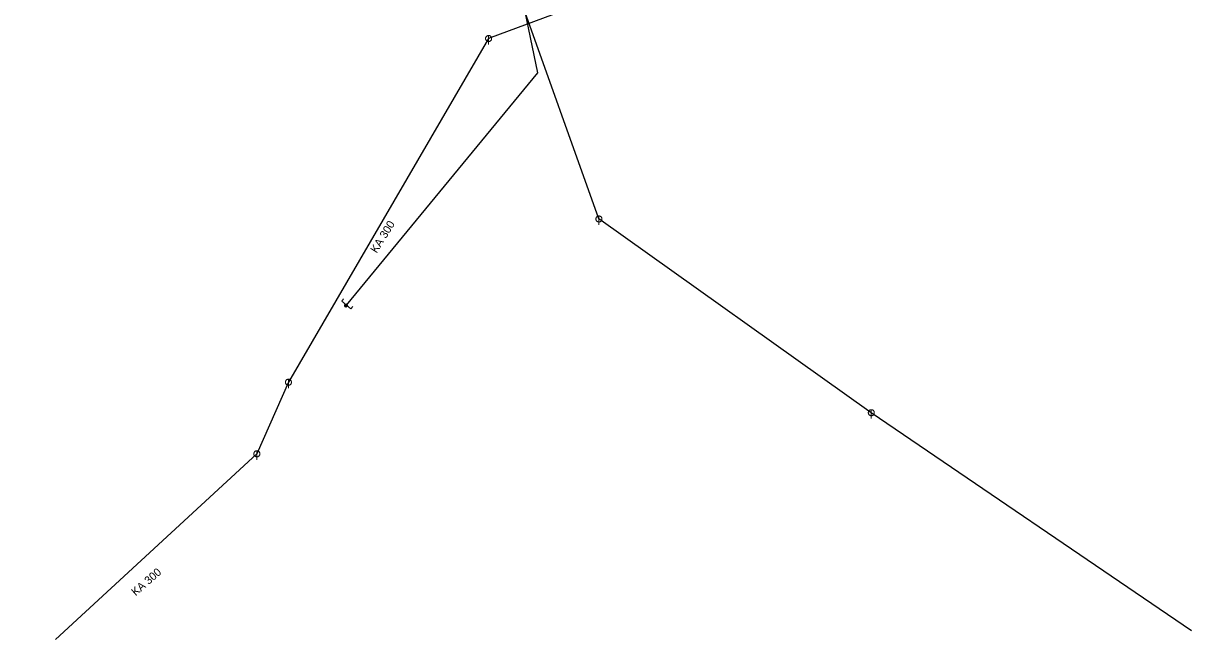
# Model space of a CAD drawing. Extents: x -687468 to -685917, y -974192 to -973456.
# Drawn here: x -686064.9 to -685967.6, y -973871.6 to -973820.8 of the extents above; entities that cross this region are included whole.
import ezdxf
from ezdxf.enums import TextEntityAlignment as Align

# ---------------------------------------------------------------- set-up
doc = ezdxf.new("R2010")
doc.units = 0
doc.header["$LTSCALE"] = 0.27
for name, color, linetype, lineweight in [('1', 7, 'Continuous', 13), ('14', 7, 'Continuous', 25), ('17', 7, 'Continuous', 25), ('22', 7, 'Continuous', 13), ('47', 7, 'Continuous', 13), ('9', 7, 'Continuous', 13)]:
    doc.layers.add(name, color=color, linetype=linetype, lineweight=lineweight)

msp = doc.modelspace()

# ---------------------------------------------------------------- linework, layer by layer
at = {"layer": '14'}
for p, q in [((-686000.392, -973812.491), (-686026.164, -973822.081)), ((-686016.971, -973837.108), (-686025.047, -973814.512)), ((-686026.164, -973822.081), (-686042.841, -973850.704)), ((-685994.278, -973853.239), (-686016.971, -973837.108)), ((-686042.841, -973850.704), (-686045.47, -973856.659)), ((-685967.589, -973871.408), (-685994.278, -973853.239)), ((-686045.47, -973856.659), (-686062.261, -973872.109))]:
    msp.add_line(p, q, dxfattribs=at)
at = {"layer": '14', "lineweight": 13}
msp.add_line((-686038.017, -973844.276), (-686038.046, -973844.313), dxfattribs=at)
at = {"layer": '17'}
msp.add_lwpolyline([(-686097.397, -973770.949), (-686068.427, -973778.603), (-686030.059, -973797.083), (-686024.092, -973815.278), (-686022.102, -973824.943), (-686038.017, -973844.276)], dxfattribs=at)
at = {"layer": '22'}
for p, q in [((-686026.163, -973821.829), (-686026.164, -973822.573)), ((-686016.97, -973836.856), (-686016.971, -973837.6)), ((-686042.84, -973850.452), (-686042.841, -973851.196)), ((-685994.277, -973852.987), (-685994.278, -973853.73)), ((-686045.469, -973856.407), (-686045.47, -973857.151))]:
    msp.add_line(p, q, dxfattribs=at)
for points in [[(-686025.912, -973822.081), (-686025.913, -973822.055), (-686025.917, -973822.029), (-686025.923, -973822.003), (-686025.933, -973821.979), (-686025.945, -973821.955), (-686025.959, -973821.933), (-686025.976, -973821.912), (-686025.994, -973821.894), (-686026.015, -973821.877), (-686026.037, -973821.863), (-686026.061, -973821.851), (-686026.085, -973821.841), (-686026.111, -973821.835), (-686026.137, -973821.831), (-686026.163, -973821.829), (-686026.189, -973821.83), (-686026.215, -973821.834), (-686026.241, -973821.84), (-686026.266, -973821.85), (-686026.289, -973821.862), (-686026.311, -973821.876), (-686026.332, -973821.893), (-686026.35, -973821.911), (-686026.367, -973821.932), (-686026.381, -973821.954), (-686026.393, -973821.978), (-686026.403, -973822.002), (-686026.41, -973822.028), (-686026.414, -973822.054), (-686026.416, -973822.08), (-686026.415, -973822.106), (-686026.411, -973822.132), (-686026.404, -973822.158), (-686026.394, -973822.183), (-686026.382, -973822.206), (-686026.368, -973822.228), (-686026.351, -973822.249), (-686026.333, -973822.267), (-686026.312, -973822.284), (-686026.29, -973822.298), (-686026.267, -973822.31), (-686026.242, -973822.32), (-686026.216, -973822.327), (-686026.19, -973822.331), (-686026.164, -973822.333), (-686026.138, -973822.332), (-686026.112, -973822.328), (-686026.086, -973822.321), (-686026.062, -973822.311), (-686026.038, -973822.299), (-686026.016, -973822.285), (-686025.995, -973822.268), (-686025.977, -973822.25), (-686025.96, -973822.229), (-686025.946, -973822.207), (-686025.934, -973822.184), (-686025.924, -973822.159), (-686025.918, -973822.133), (-686025.914, -973822.107)], [(-686016.719, -973837.108), (-686016.72, -973837.082), (-686016.724, -973837.056), (-686016.73, -973837.03), (-686016.74, -973837.006), (-686016.752, -973836.982), (-686016.766, -973836.96), (-686016.783, -973836.939), (-686016.801, -973836.921), (-686016.822, -973836.904), (-686016.844, -973836.89), (-686016.868, -973836.878), (-686016.892, -973836.868), (-686016.918, -973836.862), (-686016.944, -973836.858), (-686016.97, -973836.856), (-686016.996, -973836.857), (-686017.022, -973836.861), (-686017.048, -973836.867), (-686017.073, -973836.877), (-686017.096, -973836.889), (-686017.118, -973836.903), (-686017.139, -973836.92), (-686017.157, -973836.938), (-686017.174, -973836.959), (-686017.188, -973836.981), (-686017.2, -973837.005), (-686017.21, -973837.029), (-686017.217, -973837.055), (-686017.221, -973837.081), (-686017.223, -973837.107), (-686017.222, -973837.133), (-686017.218, -973837.159), (-686017.211, -973837.185), (-686017.201, -973837.21), (-686017.189, -973837.233), (-686017.175, -973837.255), (-686017.158, -973837.276), (-686017.14, -973837.294), (-686017.119, -973837.311), (-686017.097, -973837.325), (-686017.074, -973837.337), (-686017.049, -973837.347), (-686017.023, -973837.354), (-686016.997, -973837.358), (-686016.971, -973837.36), (-686016.945, -973837.359), (-686016.919, -973837.355), (-686016.893, -973837.348), (-686016.869, -973837.338), (-686016.845, -973837.326), (-686016.823, -973837.312), (-686016.802, -973837.295), (-686016.784, -973837.277), (-686016.767, -973837.256), (-686016.753, -973837.234), (-686016.741, -973837.211), (-686016.731, -973837.186), (-686016.725, -973837.16), (-686016.721, -973837.134)], [(-686042.589, -973850.704), (-686042.59, -973850.678), (-686042.594, -973850.652), (-686042.6, -973850.626), (-686042.61, -973850.602), (-686042.622, -973850.578), (-686042.636, -973850.556), (-686042.653, -973850.535), (-686042.671, -973850.517), (-686042.692, -973850.5), (-686042.714, -973850.486), (-686042.738, -973850.474), (-686042.762, -973850.464), (-686042.788, -973850.458), (-686042.814, -973850.454), (-686042.84, -973850.452), (-686042.866, -973850.453), (-686042.892, -973850.457), (-686042.918, -973850.463), (-686042.943, -973850.473), (-686042.966, -973850.485), (-686042.988, -973850.499), (-686043.009, -973850.516), (-686043.027, -973850.534), (-686043.044, -973850.555), (-686043.058, -973850.577), (-686043.07, -973850.601), (-686043.08, -973850.625), (-686043.087, -973850.651), (-686043.091, -973850.677), (-686043.093, -973850.703), (-686043.092, -973850.729), (-686043.088, -973850.755), (-686043.081, -973850.781), (-686043.071, -973850.806), (-686043.059, -973850.829), (-686043.045, -973850.851), (-686043.028, -973850.872), (-686043.01, -973850.89), (-686042.989, -973850.907), (-686042.967, -973850.921), (-686042.944, -973850.933), (-686042.919, -973850.943), (-686042.893, -973850.95), (-686042.867, -973850.954), (-686042.841, -973850.956), (-686042.815, -973850.955), (-686042.789, -973850.951), (-686042.763, -973850.944), (-686042.739, -973850.934), (-686042.715, -973850.922), (-686042.693, -973850.908), (-686042.672, -973850.891), (-686042.654, -973850.873), (-686042.637, -973850.852), (-686042.623, -973850.83), (-686042.611, -973850.807), (-686042.601, -973850.782), (-686042.595, -973850.756), (-686042.591, -973850.73)], [(-685994.026, -973853.239), (-685994.027, -973853.213), (-685994.031, -973853.187), (-685994.037, -973853.161), (-685994.047, -973853.137), (-685994.059, -973853.113), (-685994.073, -973853.091), (-685994.09, -973853.07), (-685994.108, -973853.052), (-685994.129, -973853.035), (-685994.151, -973853.021), (-685994.175, -973853.009), (-685994.199, -973852.999), (-685994.225, -973852.993), (-685994.251, -973852.989), (-685994.277, -973852.987), (-685994.303, -973852.988), (-685994.329, -973852.992), (-685994.355, -973852.998), (-685994.38, -973853.008), (-685994.403, -973853.02), (-685994.425, -973853.034), (-685994.446, -973853.051), (-685994.464, -973853.069), (-685994.481, -973853.09), (-685994.495, -973853.112), (-685994.507, -973853.136), (-685994.517, -973853.16), (-685994.524, -973853.186), (-685994.528, -973853.212), (-685994.53, -973853.238), (-685994.529, -973853.264), (-685994.525, -973853.29), (-685994.518, -973853.316), (-685994.508, -973853.341), (-685994.496, -973853.364), (-685994.482, -973853.386), (-685994.465, -973853.407), (-685994.447, -973853.425), (-685994.426, -973853.442), (-685994.404, -973853.456), (-685994.381, -973853.468), (-685994.356, -973853.478), (-685994.33, -973853.485), (-685994.304, -973853.489), (-685994.278, -973853.49), (-685994.252, -973853.49), (-685994.226, -973853.486), (-685994.2, -973853.479), (-685994.176, -973853.469), (-685994.152, -973853.457), (-685994.13, -973853.443), (-685994.109, -973853.426), (-685994.091, -973853.408), (-685994.074, -973853.387), (-685994.06, -973853.365), (-685994.048, -973853.342), (-685994.038, -973853.317), (-685994.032, -973853.291), (-685994.028, -973853.265)], [(-686045.218, -973856.659), (-686045.219, -973856.633), (-686045.223, -973856.607), (-686045.229, -973856.581), (-686045.239, -973856.557), (-686045.251, -973856.533), (-686045.265, -973856.511), (-686045.282, -973856.49), (-686045.3, -973856.472), (-686045.321, -973856.455), (-686045.343, -973856.441), (-686045.367, -973856.429), (-686045.391, -973856.419), (-686045.417, -973856.413), (-686045.443, -973856.409), (-686045.469, -973856.407), (-686045.495, -973856.408), (-686045.521, -973856.412), (-686045.547, -973856.418), (-686045.572, -973856.428), (-686045.595, -973856.44), (-686045.617, -973856.454), (-686045.638, -973856.471), (-686045.656, -973856.489), (-686045.673, -973856.51), (-686045.687, -973856.532), (-686045.699, -973856.556), (-686045.709, -973856.58), (-686045.716, -973856.606), (-686045.72, -973856.632), (-686045.722, -973856.658), (-686045.721, -973856.684), (-686045.717, -973856.71), (-686045.71, -973856.736), (-686045.7, -973856.761), (-686045.688, -973856.784), (-686045.674, -973856.806), (-686045.657, -973856.827), (-686045.639, -973856.845), (-686045.618, -973856.862), (-686045.596, -973856.876), (-686045.573, -973856.888), (-686045.548, -973856.898), (-686045.522, -973856.905), (-686045.496, -973856.909), (-686045.47, -973856.911), (-686045.444, -973856.91), (-686045.418, -973856.906), (-686045.392, -973856.899), (-686045.368, -973856.889), (-686045.344, -973856.877), (-686045.322, -973856.863), (-686045.301, -973856.846), (-686045.283, -973856.828), (-686045.266, -973856.807), (-686045.252, -973856.785), (-686045.24, -973856.762), (-686045.23, -973856.737), (-686045.224, -973856.711), (-686045.22, -973856.685)]]:
    msp.add_lwpolyline(points, close=True, dxfattribs=at)
at = {"layer": '47'}
msp.add_lwpolyline([(-686037.473, -973844.396), (-686037.634, -973844.591), (-686038.399, -973843.96), (-686038.239, -973843.766)], dxfattribs=at)
at = {"layer": '9'}
for points in [[(-686037.919, -973844.313), (-686037.921, -973844.299), (-686037.923, -973844.287), (-686037.926, -973844.274), (-686037.931, -973844.262), (-686037.936, -973844.25), (-686037.944, -973844.239), (-686037.951, -973844.228), (-686037.962, -973844.218), (-686037.972, -973844.211), (-686037.983, -973844.203), (-686037.995, -973844.198), (-686038.007, -973844.193), (-686038.02, -973844.19), (-686038.032, -973844.188), (-686038.046, -973844.186), (-686038.059, -973844.188), (-686038.071, -973844.19), (-686038.085, -973844.193), (-686038.097, -973844.198), (-686038.108, -973844.203), (-686038.12, -973844.211), (-686038.13, -973844.218), (-686038.14, -973844.228), (-686038.147, -973844.239), (-686038.155, -973844.25), (-686038.161, -973844.262), (-686038.166, -973844.274), (-686038.169, -973844.287), (-686038.171, -973844.299), (-686038.172, -973844.313), (-686038.171, -973844.326), (-686038.169, -973844.338), (-686038.166, -973844.352), (-686038.161, -973844.364), (-686038.155, -973844.375), (-686038.147, -973844.387), (-686038.14, -973844.397), (-686038.13, -973844.407), (-686038.12, -973844.414), (-686038.108, -973844.422), (-686038.097, -973844.428), (-686038.085, -973844.433), (-686038.071, -973844.436), (-686038.059, -973844.438), (-686038.046, -973844.439), (-686038.032, -973844.438), (-686038.02, -973844.436), (-686038.007, -973844.433), (-686037.995, -973844.428), (-686037.983, -973844.422), (-686037.972, -973844.414), (-686037.962, -973844.407), (-686037.951, -973844.397), (-686037.944, -973844.387), (-686037.936, -973844.375), (-686037.931, -973844.364), (-686037.926, -973844.352), (-686037.923, -973844.338), (-686037.921, -973844.326)], [(-686037.94, -973844.313), (-686037.94, -973844.301), (-686037.941, -973844.291), (-686037.945, -973844.279), (-686037.949, -973844.27), (-686037.954, -973844.26), (-686037.96, -973844.25), (-686037.967, -973844.242), (-686037.975, -973844.233), (-686037.983, -973844.227), (-686037.993, -973844.221), (-686038.003, -973844.216), (-686038.012, -973844.212), (-686038.024, -973844.208), (-686038.034, -973844.206), (-686038.046, -973844.206), (-686038.057, -973844.206), (-686038.068, -973844.208), (-686038.079, -973844.212), (-686038.088, -973844.216), (-686038.098, -973844.221), (-686038.108, -973844.227), (-686038.117, -973844.233), (-686038.125, -973844.242), (-686038.132, -973844.25), (-686038.137, -973844.26), (-686038.142, -973844.27), (-686038.147, -973844.279), (-686038.15, -973844.291), (-686038.152, -973844.301), (-686038.152, -973844.313), (-686038.152, -973844.324), (-686038.15, -973844.335), (-686038.147, -973844.346), (-686038.142, -973844.355), (-686038.137, -973844.365), (-686038.132, -973844.375), (-686038.125, -973844.384), (-686038.117, -973844.392), (-686038.108, -973844.399), (-686038.098, -973844.404), (-686038.088, -973844.409), (-686038.079, -973844.414), (-686038.068, -973844.417), (-686038.057, -973844.419), (-686038.046, -973844.419), (-686038.034, -973844.419), (-686038.024, -973844.417), (-686038.012, -973844.414), (-686038.003, -973844.409), (-686037.993, -973844.404), (-686037.983, -973844.399), (-686037.975, -973844.392), (-686037.967, -973844.384), (-686037.96, -973844.375), (-686037.954, -973844.365), (-686037.949, -973844.355), (-686037.945, -973844.346), (-686037.941, -973844.335), (-686037.94, -973844.324)], [(-686037.958, -973844.313), (-686037.96, -973844.304), (-686037.961, -973844.294), (-686037.963, -973844.286), (-686037.967, -973844.277), (-686037.971, -973844.27), (-686037.976, -973844.262), (-686037.982, -973844.255), (-686037.988, -973844.249), (-686037.995, -973844.243), (-686038.003, -973844.238), (-686038.011, -973844.233), (-686038.019, -973844.23), (-686038.027, -973844.228), (-686038.037, -973844.227), (-686038.046, -973844.225), (-686038.054, -973844.227), (-686038.064, -973844.228), (-686038.073, -973844.23), (-686038.081, -973844.233), (-686038.088, -973844.238), (-686038.097, -973844.243), (-686038.103, -973844.249), (-686038.11, -973844.255), (-686038.115, -973844.262), (-686038.12, -973844.27), (-686038.125, -973844.277), (-686038.128, -973844.286), (-686038.13, -973844.294), (-686038.132, -973844.304), (-686038.133, -973844.313), (-686038.132, -973844.321), (-686038.13, -973844.331), (-686038.128, -973844.34), (-686038.125, -973844.348), (-686038.12, -973844.355), (-686038.115, -973844.364), (-686038.11, -973844.37), (-686038.103, -973844.377), (-686038.097, -973844.382), (-686038.088, -973844.387), (-686038.081, -973844.392), (-686038.073, -973844.395), (-686038.064, -973844.397), (-686038.054, -973844.399), (-686038.046, -973844.4), (-686038.037, -973844.399), (-686038.027, -973844.397), (-686038.019, -973844.395), (-686038.011, -973844.392), (-686038.003, -973844.387), (-686037.995, -973844.382), (-686037.988, -973844.377), (-686037.982, -973844.37), (-686037.976, -973844.364), (-686037.971, -973844.355), (-686037.967, -973844.348), (-686037.963, -973844.34), (-686037.961, -973844.331), (-686037.96, -973844.321)], [(-686037.978, -973844.313), (-686037.978, -973844.306), (-686037.981, -973844.299), (-686037.982, -973844.292), (-686037.985, -973844.286), (-686037.988, -973844.279), (-686037.992, -973844.274), (-686037.995, -973844.267), (-686038, -973844.262), (-686038.007, -973844.259), (-686038.012, -973844.255), (-686038.019, -973844.252), (-686038.025, -973844.249), (-686038.032, -973844.248), (-686038.039, -973844.245), (-686038.046, -973844.245), (-686038.053, -973844.245), (-686038.059, -973844.248), (-686038.066, -973844.249), (-686038.073, -973844.252), (-686038.08, -973844.255), (-686038.085, -973844.259), (-686038.091, -973844.262), (-686038.096, -973844.267), (-686038.1, -973844.274), (-686038.103, -973844.279), (-686038.107, -973844.286), (-686038.11, -973844.292), (-686038.112, -973844.299), (-686038.113, -973844.306), (-686038.113, -973844.313), (-686038.113, -973844.32), (-686038.112, -973844.326), (-686038.11, -973844.333), (-686038.107, -973844.34), (-686038.103, -973844.347), (-686038.1, -973844.352), (-686038.096, -973844.358), (-686038.091, -973844.363), (-686038.085, -973844.367), (-686038.08, -973844.37), (-686038.073, -973844.374), (-686038.066, -973844.377), (-686038.059, -973844.379), (-686038.053, -973844.38), (-686038.046, -973844.38), (-686038.039, -973844.38), (-686038.032, -973844.379), (-686038.025, -973844.377), (-686038.019, -973844.374), (-686038.012, -973844.37), (-686038.007, -973844.367), (-686038, -973844.363), (-686037.995, -973844.358), (-686037.992, -973844.352), (-686037.988, -973844.347), (-686037.985, -973844.34), (-686037.982, -973844.333), (-686037.981, -973844.326), (-686037.978, -973844.32)], [(-686037.999, -973844.313), (-686037.999, -973844.308), (-686038, -973844.303), (-686038, -973844.298), (-686038.003, -973844.294), (-686038.005, -973844.289), (-686038.008, -973844.284), (-686038.011, -973844.282), (-686038.015, -973844.277), (-686038.017, -973844.275), (-686038.022, -973844.272), (-686038.027, -973844.27), (-686038.031, -973844.267), (-686038.036, -973844.267), (-686038.041, -973844.266), (-686038.046, -973844.266), (-686038.051, -973844.266), (-686038.056, -973844.267), (-686038.061, -973844.267), (-686038.065, -973844.27), (-686038.07, -973844.272), (-686038.074, -973844.275), (-686038.078, -973844.277), (-686038.081, -973844.282), (-686038.083, -973844.284), (-686038.087, -973844.289), (-686038.088, -973844.294), (-686038.091, -973844.298), (-686038.092, -973844.303), (-686038.093, -973844.308), (-686038.093, -973844.313), (-686038.093, -973844.318), (-686038.092, -973844.323), (-686038.091, -973844.328), (-686038.088, -973844.331), (-686038.087, -973844.337), (-686038.083, -973844.341), (-686038.081, -973844.345), (-686038.078, -973844.348), (-686038.074, -973844.35), (-686038.07, -973844.353), (-686038.065, -973844.355), (-686038.061, -973844.358), (-686038.056, -973844.358), (-686038.051, -973844.36), (-686038.046, -973844.36), (-686038.041, -973844.36), (-686038.036, -973844.358), (-686038.031, -973844.358), (-686038.027, -973844.355), (-686038.022, -973844.353), (-686038.017, -973844.35), (-686038.015, -973844.348), (-686038.011, -973844.345), (-686038.008, -973844.341), (-686038.005, -973844.337), (-686038.003, -973844.331), (-686038, -973844.328), (-686038, -973844.323), (-686037.999, -973844.318)], [(-686038.019, -973844.313), (-686038.019, -973844.309), (-686038.019, -973844.306), (-686038.02, -973844.304), (-686038.021, -973844.301), (-686038.022, -973844.299), (-686038.024, -973844.297), (-686038.026, -973844.294), (-686038.027, -973844.293), (-686038.03, -973844.291), (-686038.032, -973844.289), (-686038.034, -973844.288), (-686038.038, -973844.287), (-686038.039, -973844.286), (-686038.043, -973844.286), (-686038.046, -973844.286), (-686038.049, -973844.286), (-686038.052, -973844.286), (-686038.054, -973844.287), (-686038.057, -973844.288), (-686038.059, -973844.289), (-686038.061, -973844.291), (-686038.065, -973844.293), (-686038.066, -973844.294), (-686038.068, -973844.297), (-686038.07, -973844.299), (-686038.071, -973844.301), (-686038.071, -973844.304), (-686038.073, -973844.306), (-686038.073, -973844.309), (-686038.074, -973844.313), (-686038.073, -973844.316), (-686038.073, -973844.319), (-686038.071, -973844.321), (-686038.071, -973844.324), (-686038.07, -973844.326), (-686038.068, -973844.328), (-686038.066, -973844.331), (-686038.065, -973844.333), (-686038.061, -973844.335), (-686038.059, -973844.337), (-686038.057, -973844.338), (-686038.054, -973844.338), (-686038.052, -973844.34), (-686038.049, -973844.34), (-686038.046, -973844.341), (-686038.043, -973844.34), (-686038.039, -973844.34), (-686038.038, -973844.338), (-686038.034, -973844.338), (-686038.032, -973844.337), (-686038.03, -973844.335), (-686038.027, -973844.333), (-686038.026, -973844.331), (-686038.024, -973844.328), (-686038.022, -973844.326), (-686038.021, -973844.324), (-686038.02, -973844.321), (-686038.019, -973844.319), (-686038.019, -973844.316)], [(-686038.038, -973844.313), (-686038.038, -973844.311), (-686038.038, -973844.311), (-686038.039, -973844.311), (-686038.039, -973844.309), (-686038.039, -973844.309), (-686038.039, -973844.308), (-686038.039, -973844.308), (-686038.041, -973844.306), (-686038.041, -973844.306), (-686038.042, -973844.306), (-686038.043, -973844.306), (-686038.044, -973844.306), (-686038.044, -973844.304), (-686038.044, -973844.304), (-686038.046, -973844.304), (-686038.047, -973844.304), (-686038.048, -973844.304), (-686038.048, -973844.306), (-686038.049, -973844.306), (-686038.049, -973844.306), (-686038.051, -973844.306), (-686038.051, -973844.306), (-686038.052, -973844.308), (-686038.052, -973844.308), (-686038.053, -973844.309), (-686038.053, -973844.309), (-686038.054, -973844.311), (-686038.054, -973844.311), (-686038.054, -973844.311), (-686038.054, -973844.313), (-686038.054, -973844.314), (-686038.054, -973844.315), (-686038.054, -973844.315), (-686038.053, -973844.316), (-686038.053, -973844.316), (-686038.052, -973844.318), (-686038.052, -973844.318), (-686038.051, -973844.319), (-686038.051, -973844.319), (-686038.049, -973844.32), (-686038.049, -973844.32), (-686038.048, -973844.321), (-686038.048, -973844.321), (-686038.047, -973844.321), (-686038.046, -973844.321), (-686038.044, -973844.321), (-686038.044, -973844.321), (-686038.044, -973844.321), (-686038.043, -973844.32), (-686038.042, -973844.32), (-686038.041, -973844.319), (-686038.041, -973844.319), (-686038.039, -973844.318), (-686038.039, -973844.318), (-686038.039, -973844.316), (-686038.039, -973844.316), (-686038.039, -973844.315), (-686038.038, -973844.315), (-686038.038, -973844.314)]]:
    msp.add_lwpolyline(points, close=True, dxfattribs=at)

# ---------------------------------------------------------------- texts
at = {"layer": '1'}
for rotation, p in [(58, (-686034.715, -973838.761)), (41, (-686054.467, -973867.571))]:
    msp.add_text('KA 300', height=0.6667, rotation=rotation, dxfattribs=at).set_placement(p, align=Align.CENTER)

doc.saveas('drawing.dxf')
